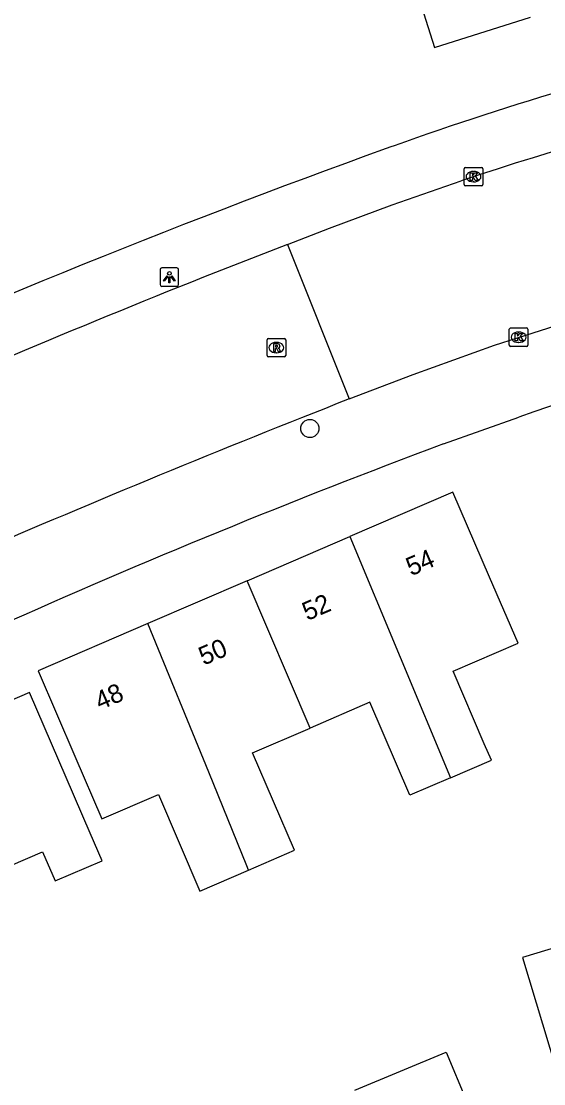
# Model space of a CAD drawing. Extents: x 160158 to 160921, y 381517 to 382041.
# Drawn here: x 160403.6 to 160431.8, y 381664.2 to 381721.4 of the extents above; entities that cross this region are included whole.
import ezdxf

# ---------------------------------------------------------------- set-up
doc = ezdxf.new("R2010")
doc.units = 0
for name, color, linetype in [('IMGEO_Boom', 7, 'Continuous'), ('IMGEO_Kolk', 7, 'Continuous'), ('IMGEO_Lichtpunt', 7, 'Continuous'), ('IMGEO_Muur', 7, 'Continuous'), ('IMGEO_Pand', 7, 'Continuous'), ('IMGEO_Pand_nummerreeks', 7, 'Continuous'), ('IMGEO_Rijbaan_lokaal_open', 7, 'Continuous'), ('IMGEO_Rioolput', 7, 'Continuous'), ('IMGEO_Voetpad_open', 7, 'Continuous')]:
    doc.layers.add(name, color=color, linetype=linetype)

msp = doc.modelspace()

# ---------------------------------------------------------------- linework, layer by layer
at = {"layer": 'IMGEO_Boom'}
msp.add_circle((160419.184, 381699.459), 0.489, dxfattribs=at)
at = {"layer": 'IMGEO_Kolk'}
for p, q in [((160427.568, 381713.525), (160428.42, 381713.525)), ((160427.493, 381712.599), (160427.493, 381713.451)), ((160427.981, 381713.305), (160428.006, 381713.305)), ((160428.494, 381713.451), (160428.494, 381712.599)), ((160428.42, 381712.525), (160427.568, 381712.525)), ((160428.004, 381712.745), (160427.979, 381712.745)), ((160429.919, 381703.95), (160429.919, 381704.802)), ((160429.994, 381704.876), (160430.846, 381704.876)), ((160430.407, 381704.656), (160430.432, 381704.656)), ((160430.92, 381704.802), (160430.92, 381703.95)), ((160430.846, 381703.876), (160429.994, 381703.876)), ((160430.43, 381704.096), (160430.405, 381704.096))]:
    msp.add_line(p, q, dxfattribs=at)
for points in [[(160427.568, 381713.525), (160428.42, 381713.525)], [(160427.493, 381712.599), (160427.493, 381713.451)], [(160427.814, 381713.225), (160427.937, 381713.225), (160427.937, 381713.074), (160428.067, 381713.225), (160428.231, 381713.225), (160428.085, 381713.074), (160428.238, 381712.825), (160428.086, 381712.825), (160428.001, 381712.989), (160427.937, 381712.922), (160427.937, 381712.825), (160427.814, 381712.825), (160427.814, 381713.225)], [(160428.494, 381713.451), (160428.494, 381712.599)], [(160428.42, 381712.525), (160427.568, 381712.525)], [(160429.919, 381703.95), (160429.919, 381704.802)], [(160429.994, 381704.876), (160430.846, 381704.876)], [(160430.24, 381704.576), (160430.363, 381704.576), (160430.363, 381704.425), (160430.493, 381704.576), (160430.657, 381704.576), (160430.511, 381704.425), (160430.664, 381704.176), (160430.512, 381704.176), (160430.427, 381704.34), (160430.363, 381704.273), (160430.363, 381704.176), (160430.24, 381704.176), (160430.24, 381704.576)], [(160430.92, 381704.802), (160430.92, 381703.95)], [(160430.846, 381703.876), (160429.994, 381703.876)]]:
    msp.add_lwpolyline(points, dxfattribs=at)
for centre, start, end in [((160427.57, 381713.449), 91.552, 178.448), ((160427.57, 381713.449), 91.552, 178.448), ((160428.418, 381713.449), 1.552, 88.448), ((160428.418, 381713.449), 1.552, 88.448), ((160427.57, 381712.601), 181.552, 268.448), ((160427.57, 381712.601), 181.552, 268.448), ((160428.418, 381712.601), 271.552, 358.448), ((160428.418, 381712.601), 271.552, 358.448), ((160429.996, 381704.8), 91.552, 178.448), ((160429.996, 381704.8), 91.552, 178.448), ((160430.844, 381704.8), 1.552, 88.448), ((160430.844, 381704.8), 1.552, 88.448), ((160429.996, 381703.952), 181.552, 268.448), ((160429.996, 381703.952), 181.552, 268.448), ((160430.844, 381703.952), 271.552, 358.448), ((160430.844, 381703.952), 271.552, 358.448)]:
    msp.add_arc(centre, 0.0765, start, end, dxfattribs=at)
for centre, major_axis, ratio, start_param, end_param in [((160427.98, 381713.025), (-0.387, 0.002), 0.722429, 4.712389, 7.853982), ((160428.005, 381713.025), (-0.39, 0.002), 0.717154, 1.570796, 4.712389), ((160430.406, 381704.376), (-0.387, 0.002), 0.722429, 4.712389, 7.853982), ((160430.431, 381704.376), (-0.39, 0.002), 0.717154, 1.570796, 4.712389)]:
    msp.add_ellipse(centre, major_axis=major_axis, ratio=ratio, start_param=start_param, end_param=end_param, dxfattribs=at)
at = {"layer": 'IMGEO_Lichtpunt'}
for p, q in [((160411.119, 381708.018), (160411.119, 381707.211)), ((160411.119, 381708.018), (160411.119, 381707.211)), ((160412.021, 381708.113), (160411.213, 381708.113)), ((160412.021, 381708.113), (160411.213, 381708.113)), ((160412.115, 381707.211), (160412.115, 381708.018)), ((160412.115, 381707.211), (160412.115, 381708.018)), ((160411.213, 381707.117), (160412.021, 381707.117)), ((160411.213, 381707.117), (160412.021, 381707.117))]:
    msp.add_line(p, q, dxfattribs=at)
for points in [[(160411.493, 381707.682), (160411.532, 381707.654), (160411.344, 381707.392), (160411.306, 381707.419), (160411.493, 381707.682)], [(160411.595, 381707.634), (160411.642, 381707.634), (160411.642, 381707.312), (160411.595, 381707.312), (160411.595, 381707.634)], [(160411.705, 381707.654), (160411.743, 381707.681), (160411.93, 381707.419), (160411.891, 381707.391), (160411.705, 381707.654)]]:
    msp.add_lwpolyline(points, dxfattribs=at)
msp.add_circle((160411.618, 381707.816), 0.0994, dxfattribs=at)
for centre, start, end in [((160411.213, 381708.018), 90, 180), ((160411.213, 381708.018), 90, 180), ((160412.021, 381708.018), 0, 90), ((160412.021, 381708.018), 0, 90), ((160411.213, 381707.211), 180, 270), ((160411.213, 381707.211), 180, 270), ((160412.021, 381707.211), 270, 0), ((160412.021, 381707.211), 270, 360)]:
    msp.add_arc(centre, 0.0946, start, end, dxfattribs=at)
at = {"layer": 'IMGEO_Muur'}
msp.add_lwpolyline([(160423.537, 381714.625), (160423.295, 381714.538)], dxfattribs=at)
msp.add_arc((160579.399, 381282.334), 459.531, 109.85873, 114.51032, dxfattribs=at)
at = {"layer": 'IMGEO_Pand'}
for points in [[(160427.914, 381733.636), (160424.9, 381732.683), (160426.048, 381729.052), (160423.295, 381728.182), (160424.38, 381724.749), (160425.888, 381719.981), (160431.065, 381721.617)], [(160426.758, 381680.647), (160428.957, 381681.595), (160428.576, 381682.479), (160426.894, 381686.381), (160430.394, 381687.891), (160428.861, 381691.446), (160426.882, 381696.037), (160421.333, 381693.645)], [(160415.803, 381691.26), (160421.333, 381693.645)], [(160421.333, 381693.645), (160426.758, 381680.647)], [(160415.803, 381691.26), (160410.467, 381688.96)], [(160419.198, 381683.322), (160415.803, 381691.26)], [(160410.467, 381688.96), (160404.546, 381686.407), (160406.525, 381681.816), (160407.986, 381678.428), (160411.024, 381679.738), (160413.262, 381674.546), (160415.881, 381675.675)], [(160415.881, 381675.675), (160415.791, 381675.897), (160413.736, 381680.939), (160410.467, 381688.96)], [(160402.154, 381675.519), (160404.795, 381676.658), (160405.472, 381675.087), (160407.999, 381676.177), (160407.358, 381677.662), (160406.067, 381680.656), (160404.088, 381685.247), (160401.91, 381684.308), (160400.952, 381684.688), (160398.688, 381683.712)], [(160426.758, 381680.647), (160424.574, 381679.705), (160422.416, 381684.709), (160419.198, 381683.322)], [(160415.881, 381675.675), (160418.358, 381676.743), (160416.098, 381681.986), (160419.198, 381683.322)], [(160432.441, 381664.956), (160436.955, 381666.315), (160435.144, 381672.33), (160430.629, 381670.97), (160432.441, 381664.956)], [(160421.604, 381663.81), (160426.519, 381665.866), (160427.62, 381663.235), (160422.801, 381661.218)]]:
    msp.add_lwpolyline(points, dxfattribs=at)
at = {"layer": 'IMGEO_Rijbaan_lokaal_open'}
for points in [[(160417.976, 381709.379), (160420.233, 381710.256), (160423.622, 381711.508), (160427.334, 381712.804)], [(160417.976, 381709.379), (160421.301, 381701.05)], [(160421.301, 381701.05), (160424.748, 381702.365), (160429.125, 381703.943), (160436.56, 381706.312), (160440.846, 381707.484)]]:
    msp.add_lwpolyline(points, dxfattribs=at)
for centre, radius, start, end in [((160487.124, 381533.441), 189.066, 98.59859, 108.43577), ((160608.825, 381216.645), 528.403, 111.17271, 113.58026), ((160659.5, 381094.633), 651.521, 111.444808, 113.381413)]:
    msp.add_arc(centre, radius, start, end, dxfattribs=at)
at = {"layer": 'IMGEO_Rioolput'}
for p, q in [((160416.879, 381703.389), (160416.879, 381704.241)), ((160416.954, 381704.315), (160417.806, 381704.315)), ((160417.367, 381704.095), (160417.392, 381704.095)), ((160417.88, 381704.241), (160417.88, 381703.389)), ((160417.806, 381703.315), (160416.954, 381703.315)), ((160417.39, 381703.535), (160417.365, 381703.535))]:
    msp.add_line(p, q, dxfattribs=at)
for points in [[(160416.879, 381703.389), (160416.879, 381704.241)], [(160416.954, 381704.315), (160417.806, 381704.315)], [(160417.468, 381704.013), (160417.216, 381704.015), (160417.216, 381703.615)], [(160417.216, 381703.615), (160417.34, 381703.615), (160417.34, 381703.777), (160417.351, 381703.777)], [(160417.394, 381703.934), (160417.34, 381703.934), (160417.34, 381703.853)], [(160417.34, 381703.853), (160417.392, 381703.853)], [(160417.88, 381704.241), (160417.88, 381703.389)], [(160417.806, 381703.315), (160416.954, 381703.315)], [(160417.398, 381703.748), (160417.469, 381703.615), (160417.609, 381703.615), (160417.544, 381703.741)]]:
    msp.add_lwpolyline(points, dxfattribs=at)
for centre, radius, start, end in [((160416.956, 381704.239), 0.0765, 91.552, 178.448), ((160416.956, 381704.239), 0.0765, 91.552, 178.448), ((160417.35, 381703.724), 0.0533, 26.0293, 88.6989), ((160417.376, 381704.042), 0.19, 274.7715, 282.9687), ((160417.4, 381703.838), 0.0964, 77.0061, 93.1865), ((160417.414, 381703.895), 0.0378, 276.6634, 79.6772), ((160417.467, 381703.903), 0.109, 350.3612, 89.416), ((160417.465, 381703.903), 0.112, 277.5842, 350.9817), ((160417.449, 381703.688), 0.108, 29.5134, 73.7905), ((160417.804, 381704.239), 0.0765, 1.552, 88.448), ((160417.804, 381704.239), 0.0765, 1.552, 88.448), ((160416.956, 381703.391), 0.0765, 181.552, 268.448), ((160416.956, 381703.391), 0.0765, 181.552, 268.448), ((160417.804, 381703.391), 0.0765, 271.552, 358.448), ((160417.804, 381703.391), 0.0765, 271.552, 358.448)]:
    msp.add_arc(centre, radius, start, end, dxfattribs=at)
for centre, major_axis, ratio, start_param, end_param in [((160417.366, 381703.815), (-0.387, 0.002), 0.722429, 4.712389, 7.853982), ((160417.391, 381703.815), (-0.39, 0.002), 0.717154, 1.570796, 4.712389)]:
    msp.add_ellipse(centre, major_axis=major_axis, ratio=ratio, start_param=start_param, end_param=end_param, dxfattribs=at)
at = {"layer": 'IMGEO_Voetpad_open'}
for points in [[(160423.725, 381714.692), (160423.537, 381714.625), (160423.295, 381714.538)], [(160426.387, 381698.625), (160430.431, 381700.071)]]:
    msp.add_lwpolyline(points, dxfattribs=at)
for centre, radius, start, end in [((160482.587, 381550.022), 174.874, 102.9811, 109.66961), ((160579.399, 381282.334), 459.531, 109.85873, 114.51032), ((160482.134, 381552.43), 156.433, 99.33628, 109.29985), ((160563.843, 381329.278), 394.096, 110.4133, 117.98729)]:
    msp.add_arc(centre, radius, start, end, dxfattribs=at)

# ---------------------------------------------------------------- texts
at = {"layer": 'IMGEO_Pand_nummerreeks'}
for s, rotation, p in [('54', 23.3251, (160424.63, 381691.494)), ('52', 23.3229, (160419.043, 381689.085)), ('50', 23.3251, (160413.465, 381686.68)), ('48', 23.3251, (160407.881, 381684.273))]:
    msp.add_text(s, height=1, rotation=rotation, dxfattribs=at).set_placement(p)

doc.saveas('drawing.dxf')
